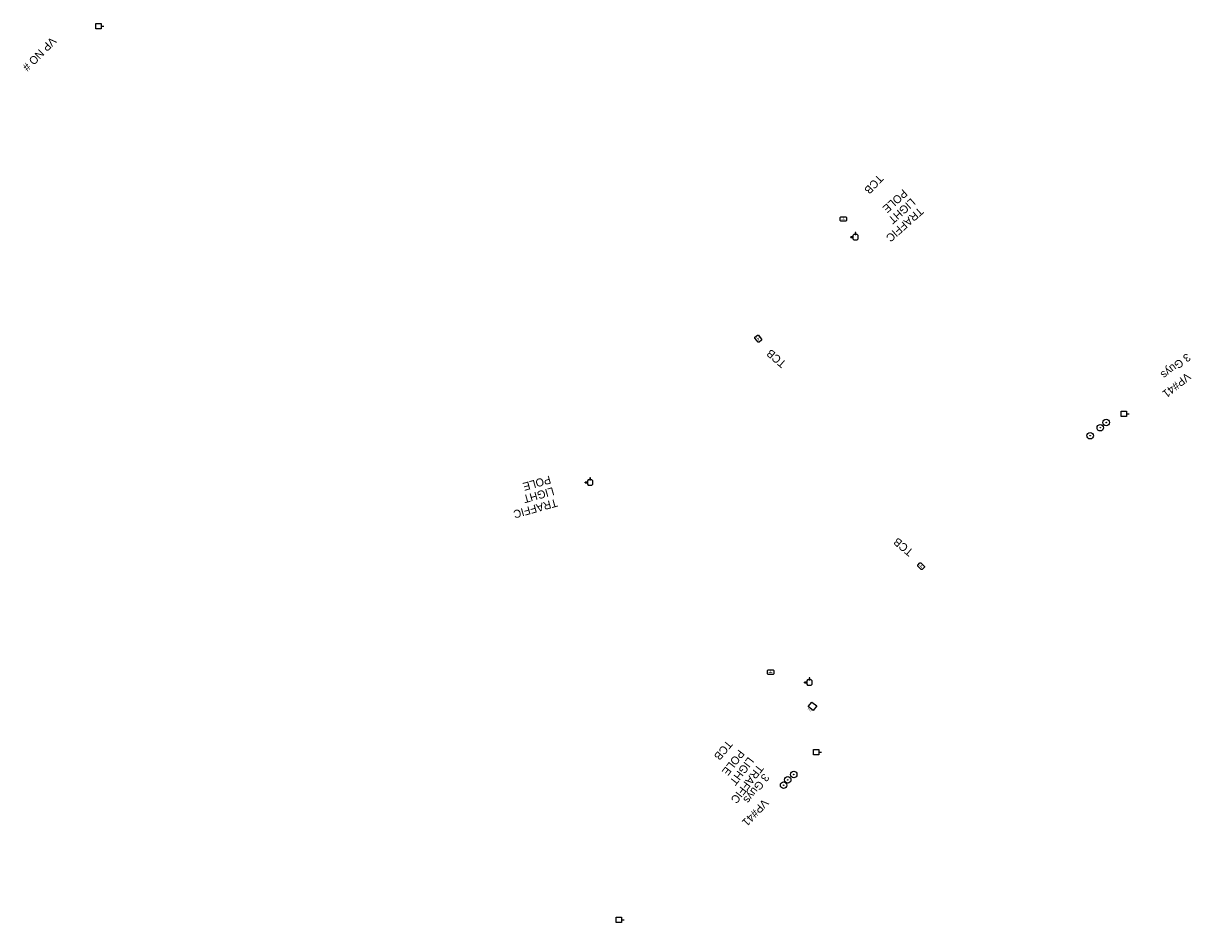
# Model space of a CAD drawing. Extents: x 3872070 to 3879223, y 293944 to 310567.
# Drawn here: x 3876534.5 to 3876972.5, y 294554.5 to 294891.7 of the extents above; entities that cross this region are included whole.
import ezdxf

# ---------------------------------------------------------------- set-up
doc = ezdxf.new("R2010")
doc.units = 0
for name, color, linetype in [('Level 34', 7, 'Continuous'), ('Level 39', 7, 'Continuous'), ('Level 4', 7, 'Continuous'), ('Level 9', 7, 'Continuous')]:
    doc.layers.add(name, color=color, linetype=linetype)

msp = doc.modelspace()

# ---------------------------------------------------------------- linework, layer by layer
at = {"layer": 'Level 4'}
for p, q in [((3876563.74, 294890.73), (3876564.74, 294890.73)), ((3876948.11, 294745.27), (3876949.11, 294745.27)), ((3876832.75, 294618.5), (3876833.75, 294618.5)), ((3876758.74, 294555.52), (3876759.74, 294555.52))]:
    msp.add_line(p, q, dxfattribs=at)
for points in [[(3876561.74, 294889.73), (3876561.74, 294891.73), (3876563.74, 294891.73), (3876563.74, 294889.73)], [(3876946.11, 294744.27), (3876946.11, 294746.27), (3876948.11, 294746.27), (3876948.11, 294744.27)], [(3876830.75, 294617.5), (3876830.75, 294619.5), (3876832.75, 294619.5), (3876832.75, 294617.5)], [(3876756.74, 294554.52), (3876756.74, 294556.52), (3876758.74, 294556.52), (3876758.74, 294554.52)]]:
    msp.add_lwpolyline(points, close=True, dxfattribs=at)
for centre, radius in [((3876938.24, 294740.11), 1.22), ((3876940.48, 294742.05), 1.22), ((3876940.48, 294742.05), 0.0992), ((3876940.48, 294742.05), 0.0483), ((3876934.46, 294737.12), 1.22), ((3876934.46, 294737.12), 0.0992), ((3876934.46, 294737.12), 0.0483), ((3876938.24, 294740.11), 0.0992), ((3876938.24, 294740.11), 0.0483), ((3876821.06, 294608.05), 1.22), ((3876823.32, 294610.06), 1.22), ((3876823.32, 294610.06), 0.0992), ((3876823.32, 294610.06), 0.0483), ((3876819.55, 294606.04), 1.22), ((3876819.55, 294606.04), 0.0992), ((3876819.55, 294606.04), 0.0483), ((3876821.06, 294608.05), 0.0992), ((3876821.06, 294608.05), 0.0483)]:
    msp.add_circle(centre, radius, dxfattribs=at)
at = {"layer": 'Level 9'}
for p, q in [((3876845.46, 294811.7), (3876844.68, 294811.7)), ((3876844.68, 294811.45), (3876844.68, 294811.7)), ((3876845.46, 294811.45), (3876844.68, 294811.45)), ((3876745.96, 294719.71), (3876745.19, 294719.71)), ((3876745.19, 294719.46), (3876745.19, 294719.71)), ((3876745.96, 294719.46), (3876745.19, 294719.46)), ((3876828.18, 294644.7), (3876827.4, 294644.7)), ((3876827.4, 294644.45), (3876827.4, 294644.7)), ((3876828.18, 294644.45), (3876827.4, 294644.45))]:
    msp.add_line(p, q, dxfattribs=at)
for points in [[(3876842.87, 294817.52), (3876840.97, 294817.52), (3876840.72, 294817.77), (3876840.72, 294818.99), (3876840.97, 294819.24), (3876842.87, 294819.24), (3876843.12, 294818.99), (3876843.12, 294817.77)], [(3876844.68, 294811.45), (3876845.46, 294811.45), (3876845.46, 294811.7), (3876844.68, 294811.7)], [(3876845.81, 294810.58), (3876847.11, 294810.58), (3876847.46, 294810.93), (3876847.46, 294812.22), (3876847.11, 294812.58), (3876845.81, 294812.58), (3876845.46, 294812.22), (3876845.46, 294810.93)], [(3876846.34, 294813.36), (3876846.34, 294812.58), (3876846.59, 294812.58), (3876846.59, 294813.36)], [(3876809.96, 294772.21), (3876808.75, 294773.68), (3876808.78, 294774.03), (3876809.73, 294774.81), (3876810.08, 294774.78), (3876811.29, 294773.31), (3876811.26, 294772.96), (3876810.31, 294772.18)], [(3876745.19, 294719.46), (3876745.97, 294719.46), (3876745.97, 294719.71), (3876745.19, 294719.71)], [(3876746.32, 294718.58), (3876747.61, 294718.58), (3876747.97, 294718.94), (3876747.97, 294720.23), (3876747.61, 294720.58), (3876746.32, 294720.58), (3876745.97, 294720.23), (3876745.96, 294718.94)], [(3876746.84, 294721.36), (3876746.84, 294720.58), (3876747.09, 294720.58), (3876747.09, 294721.36)], [(3876871.16, 294686.89), (3876869.8, 294688.23), (3876869.8, 294688.58), (3876870.66, 294689.46), (3876871.01, 294689.46), (3876872.37, 294688.12), (3876872.37, 294687.77), (3876871.51, 294686.89)], [(3876815.59, 294647.58), (3876813.68, 294647.58), (3876813.43, 294647.83), (3876813.43, 294649.05), (3876813.68, 294649.3), (3876815.59, 294649.3), (3876815.84, 294649.05), (3876815.84, 294647.83)], [(3876827.4, 294644.45), (3876828.18, 294644.45), (3876828.18, 294644.7), (3876827.4, 294644.7)], [(3876828.53, 294643.58), (3876829.83, 294643.58), (3876830.18, 294643.93), (3876830.18, 294645.22), (3876829.83, 294645.58), (3876828.53, 294645.58), (3876828.18, 294645.22), (3876828.18, 294643.93)], [(3876829.06, 294646.36), (3876829.05, 294645.58), (3876829.3, 294645.58), (3876829.3, 294646.36)], [(3876830.1, 294637.25), (3876831.99, 294635.77), (3876830.65, 294634.05), (3876828.76, 294635.52)]]:
    msp.add_lwpolyline(points, close=True, dxfattribs=at)

# ---------------------------------------------------------------- texts
at = {"layer": 'Level 34'}
for s, rotation, p in [('VP NO #', 225.585, (3876545.02, 294886.86)), ('3 Guys', 217.3106, (3876970.68, 294768.21)), ('VP#41', 218.7709, (3876970.63, 294760.97)), ('3 Guys', 231.8238, (3876812.09, 294610.67)), ('VP#41', 226.6789, (3876811.97, 294601.16))]:
    msp.add_text(s, height=3, rotation=rotation, dxfattribs=at).set_placement(p)
at = {"layer": 'Level 39'}
for s, rotation, p in [('TCB', 226.7141, (3876855, 294835.3)), ('POLE', 221.6278, (3876864.31, 294829.74)), ('LIGHT', 221.6278, (3876867.3, 294826.38)), ('TRAFFIC', 221.6278, (3876870.29, 294823.01)), ('TCB', 139.1852, (3876820.79, 294764.53)), ('POLE', 195.6674, (3876731.79, 294722.18)), ('LIGHT', 195.6674, (3876733.01, 294717.85)), ('TRAFFIC', 195.6674, (3876734.23, 294713.52)), ('TCB', 140.1109, (3876868.42, 294693.96)), ('TCB', 230.2424, (3876798.34, 294623.18)), ('POLE', 232.2611, (3876802.76, 294619.63)), ('LIGHT', 232.2611, (3876806.32, 294616.87)), ('TRAFFIC', 232.2611, (3876809.88, 294614.12))]:
    msp.add_text(s, height=3, rotation=rotation, dxfattribs=at).set_placement(p)
at = {"layer": 'Level 9'}
for s, rotation, p in [('H', 90, (3876842.62, 294817.91)), ('H', 39.5808, (3876810.11, 294772.66)), ('H', 45.4067, (3876871.26, 294687.35)), ('H', 90, (3876815.34, 294647.98)), ('E', 232, (3876829.26, 294635.48))]:
    msp.add_text(s, height=1.41, rotation=rotation, dxfattribs=at).set_placement(p)

doc.saveas('drawing.dxf')
